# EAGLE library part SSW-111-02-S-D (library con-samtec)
THROUGH-HOLE .025" SQ POST SOCKET Source: Samtec SSW.pdf
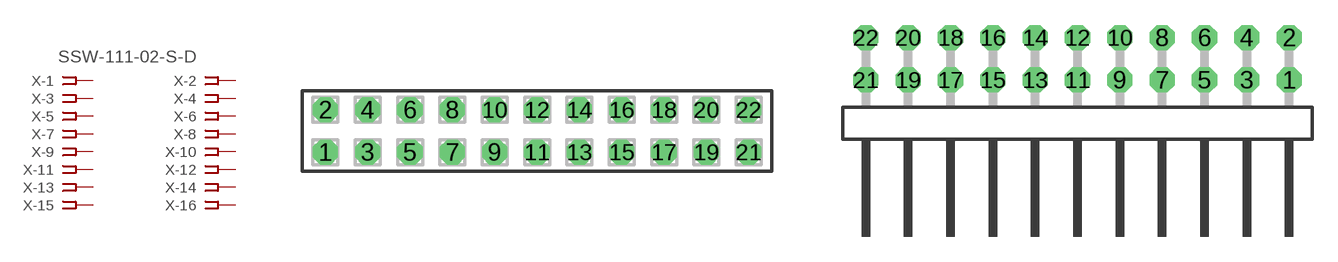
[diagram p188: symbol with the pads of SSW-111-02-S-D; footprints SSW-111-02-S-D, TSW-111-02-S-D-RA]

Designator prefix X; gates -1=FPINV -2=FPIN -3=FPIN -4=FPIN -5=FPIN -6=FPIN -7=FPIN -8=FPIN -9=FPIN -10=FPIN -11=FPIN -12=FPIN -13=FPIN -14=FPIN -15=FPIN -16=FPIN -17=FPIN -18=FPIN -19=FPIN -20=FPIN -21=FPIN -22=FPIN

## SSW-111-02-S-D (MPN: SSW-111-02-S-D; OC_FARNELL: unknown; OC_NEWARK: 11P9496)  [SSW-111-02-S-D]
1  -1:1  pas
2  -2:1  pas
3  -3:1  pas
4  -4:1  pas
5  -5:1  pas
6  -6:1  pas
7  -7:1  pas
8  -8:1  pas
9  -9:1  pas
10  -10:1  pas
11  -11:1  pas
12  -12:1  pas
13  -13:1  pas
14  -14:1  pas
15  -15:1  pas
16  -16:1  pas
17  -17:1  pas
18  -18:1  pas
19  -19:1  pas
20  -20:1  pas
21  -21:1  pas
22  -22:1  pas

## SSW-111-02-S-D-RA (MPN: SSW-111-02-S-D-RA; OC_FARNELL: unknown; OC_NEWARK: 11P9497)  [TSW-111-02-S-D-RA]
Pads as for SSW-111-02-S-D

## Footprint SSW-111-02-S-D (pad centres in mm)
THROUGH-HOLE .025" SQ POST SOCKET Source: Samtec SSW.pdf
drill 1 pad 1.5 octagon: 1 -12.7,-1.27; 2 -12.7,1.27; 3 -10.16,-1.27; 4 -10.16,1.27; 5 -7.62,-1.27; 6 -7.62,1.27; 7 -5.08,-1.27; 8 -5.08,1.27; 9 -2.54,-1.27; 10 -2.54,1.27; 11 0,-1.27; 12 0,1.27; 13 2.54,-1.27; 14 2.54,1.27; 15 5.08,-1.27; 16 5.08,1.27; 17 7.62,-1.27; 18 7.62,1.27; 19 10.16,-1.27; 20 10.16,1.27; 21 12.7,-1.27; 22 12.7,1.27

## Footprint TSW-111-02-S-D-RA (pad centres in mm)
THROUGH-HOLE .025" SQ POST HEADER Source: Samtec TSW.pdf
drill 1 pad 1.5 octagon: 1 12.7,1.524; 2 12.7,4.064; 3 10.16,1.524; 4 10.16,4.064; 5 7.62,1.524; 6 7.62,4.064; 7 5.08,1.524; 8 5.08,4.064; 9 2.54,1.524; 10 2.54,4.064; 11 0,1.524; 12 0,4.064; 13 -2.54,1.524; 14 -2.54,4.064; 15 -5.08,1.524; 16 -5.08,4.064; 17 -7.62,1.524; 18 -7.62,4.064; 19 -10.16,1.524; 20 -10.16,4.064; 21 -12.7,1.524; 22 -12.7,4.064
